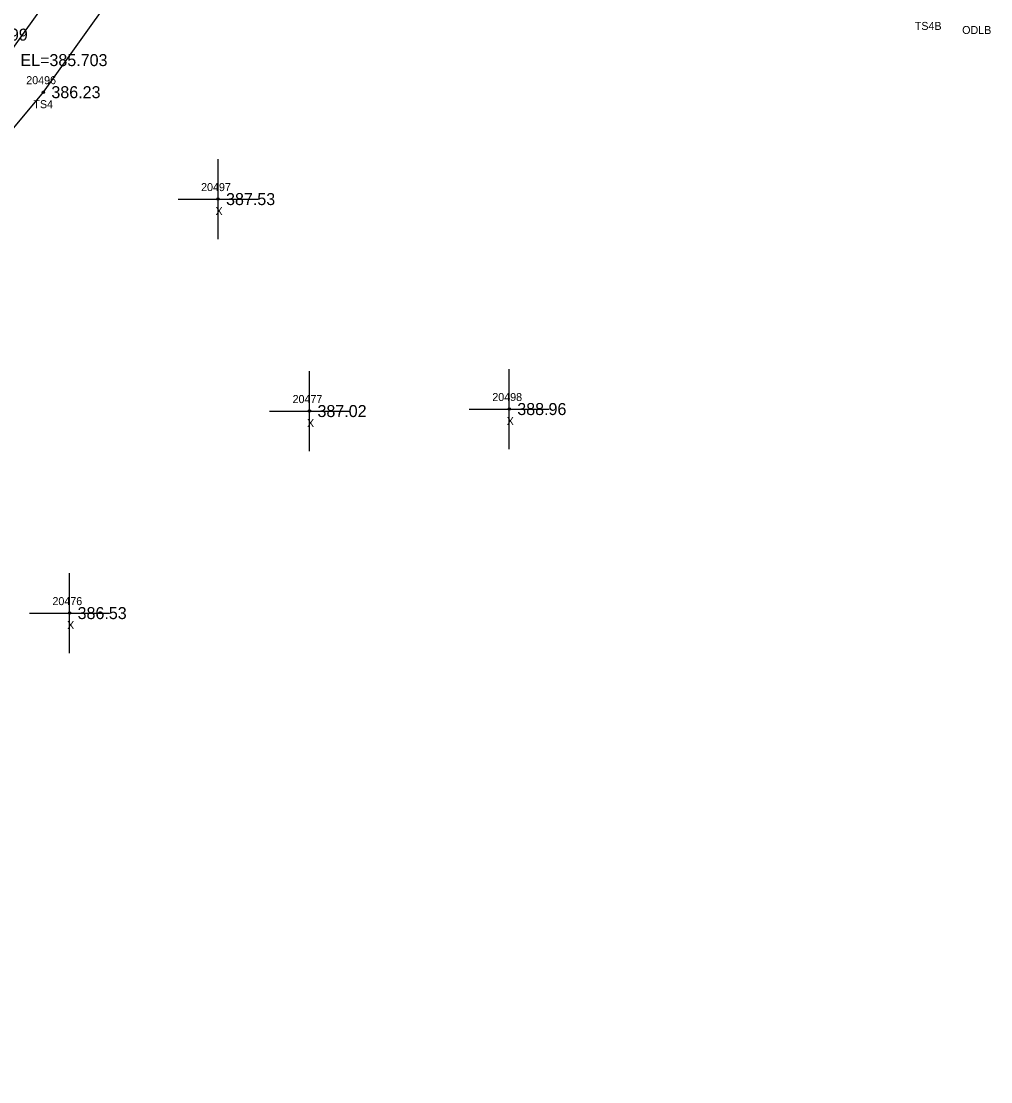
# Model space of a CAD drawing. Extents: x 2116373 to 2118139, y 979529 to 981026.
# Drawn here: x 2117884.9 to 2118006.1, y 980505.4 to 980637.9 of the extents above; entities that cross this region are included whole.
import ezdxf

# ---------------------------------------------------------------- set-up
doc = ezdxf.new("R2010")
doc.units = 0
for name, color, linetype in [('RD_DTM_BkLn2', 7, 'Continuous'), ('RD_DTM_BkLn_txCode', 7, 'Continuous'), ('RD_EX_H2O', 7, 'Continuous'), ('RD_EX_H2O_txCode', 7, 'Continuous'), ('RD_EX_Misc', 7, 'Continuous'), ('RD_EX_Misc_txCode', 7, 'Continuous'), ('RD_EX_TX_H2O_ELEV', 7, 'Continuous'), ('RD_EX_TX_Misc_ELEV', 7, 'Continuous'), ('RD_SMD_Locator', 7, 'Continuous')]:
    doc.layers.add(name, color=color, linetype=linetype)

msp = doc.modelspace()

# ---------------------------------------------------------------- linework, layer by layer
at = {"layer": 'RD_DTM_BkLn2'}
msp.add_lwpolyline([(2117734.28, 980458.87), (2117786.65, 980514.59), (2117820.54, 980553.44), (2117855.54, 980590.41), (2117887.71, 980629.08), (2117918.16, 980671.7), (2117943.36, 980714.4), (2117971.9, 980758.61), (2117977.71, 980769.98), (2117980.03, 980767.32), (2117984.46, 980744.95), (2117988.75, 980693.43), (2117998.28, 980638.86)], dxfattribs=at)
at = {"layer": 'RD_EX_H2O'}
msp.add_lwpolyline([(2117725.24, 980456.84), (2117729.88, 980462.23), (2117745.69, 980479.89), (2117783.52, 980517.46), (2117819.19, 980554.81), (2117852.43, 980593.07), (2117882.84, 980633.09), (2117913.27, 980675.65), (2117938.84, 980717.37), (2117963.41, 980761.5), (2117973.8, 980774.7), (2117982.58, 980769.22), (2117983.22, 980768.54), (2117990.51, 980745.52), (2117996.79, 980694.22), (2118004.21, 980639.35)], dxfattribs=at)
at = {"layer": 'RD_EX_Misc'}
for p, q in [((2117909.53, 980610.72), (2117909.53, 980620.72)), ((2117904.53, 980615.72), (2117914.53, 980615.72)), ((2117920.95, 980584.23), (2117920.95, 980594.23)), ((2117945.91, 980584.48), (2117945.91, 980594.48)), ((2117915.95, 980589.23), (2117925.95, 980589.23)), ((2117940.91, 980589.48), (2117950.91, 980589.48)), ((2117890.98, 980558.98), (2117890.98, 980568.98)), ((2117885.98, 980563.98), (2117895.98, 980563.98))]:
    msp.add_line(p, q, dxfattribs=at)
at = {"layer": 'RD_SMD_Locator'}
for centre in [(2117887.71, 980629.08), (2117909.53, 980615.72), (2117920.95, 980589.23), (2117945.91, 980589.48), (2117890.98, 980563.98)]:
    msp.add_circle(centre, 0.15, dxfattribs=at)

# ---------------------------------------------------------------- texts
at = {"layer": 'RD_DTM_BkLn_txCode'}
for s, p in [('TS4B', (2117996.57, 980636.86)), ('20496', (2117885.57, 980630.08)), ('TS4', (2117886.46, 980627.08))]:
    msp.add_text(s, height=1, dxfattribs=at).set_placement(p)
at = {"layer": 'RD_EX_H2O_txCode'}
msp.add_text('ODLB', height=1, dxfattribs=at).set_placement((2118002.49, 980636.35))
at = {"layer": 'RD_EX_Misc_txCode'}
for s, p in [('20497', (2117907.41, 980616.72)), ('X', (2117909.21, 980613.72)), ('20477', (2117918.84, 980590.23)), ('20498', (2117943.79, 980590.48)), ('X', (2117920.64, 980587.23)), ('X', (2117945.59, 980587.48)), ('20476', (2117888.84, 980564.98)), ('X', (2117890.67, 980561.98))]:
    msp.add_text(s, height=1, dxfattribs=at).set_placement(p)
at = {"layer": 'RD_EX_TX_H2O_ELEV'}
msp.add_text('EL=385.703', height=1.5, dxfattribs=at).set_placement((2117884.84, 980632.34))
at = {"layer": 'RD_EX_TX_Misc_ELEV'}
for s, p in [('386.99', (2117879.62, 980635.52)), ('386.23', (2117888.71, 980628.33)), ('387.53', (2117910.53, 980614.97)), ('387.02', (2117921.95, 980588.48)), ('388.96', (2117946.91, 980588.73)), ('386.53', (2117891.98, 980563.23))]:
    msp.add_text(s, height=1.5, dxfattribs=at).set_placement(p)

doc.saveas('drawing.dxf')
